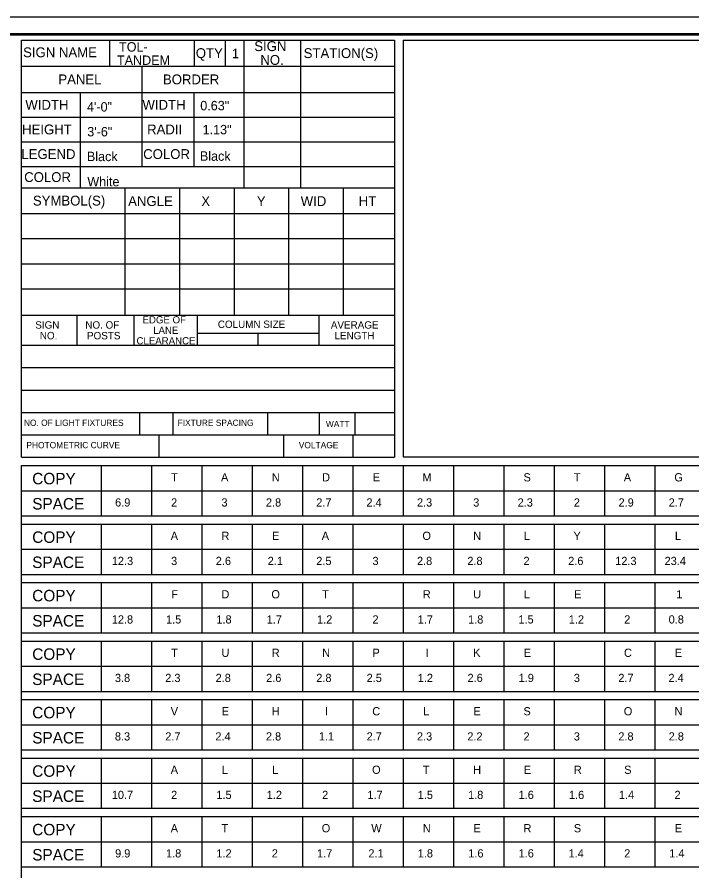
# Model space of a CAD drawing. Extents: x 17890484 to 17890754, y 17897495 to 17897992.
# Drawn here: x 17890564.9 to 17890605.3, y 17897547.8 to 17897598.9 of the extents above; entities that cross this region are included whole.
import ezdxf

# ---------------------------------------------------------------- set-up
doc = ezdxf.new("R2010")
doc.units = 0
for name, color, linetype in [('GSSign', 7, 'Continuous'), ('PlotBorder_dp', 7, 'Continuous'), ('SheetBorder_dp', 7, 'Continuous'), ('SheetLinesMisc1_dp', 7, 'Continuous'), ('SheetLinesMisc2_dp', 7, 'Continuous'), ('TextMinor', 7, 'Continuous')]:
    doc.layers.add(name, color=color, linetype=linetype)

msp = doc.modelspace()

# ---------------------------------------------------------------- linework, layer by layer
at = {"layer": 'PlotBorder_dp'}
msp.add_lwpolyline([(17890483.9, 17897494.956), (17890645.649, 17897494.956), (17890645.649, 17897598.868), (17890483.9, 17897598.868)], close=True, dxfattribs=at)
at = {"layer": 'SheetBorder_dp'}
msp.add_line((17890489.292, 17897597.887), (17890640.258, 17897597.887), dxfattribs=at)
at = {"layer": 'SheetLinesMisc1_dp'}
for p, q in [((17890570.448, 17897595.928), (17890570.448, 17897597.496)), ((17890575.495, 17897597.496), (17890575.495, 17897595.928)), ((17890577.348, 17897597.496), (17890577.348, 17897595.928)), ((17890578.452, 17897597.496), (17890578.452, 17897588.662)), ((17890581.847, 17897597.496), (17890581.847, 17897588.662)), ((17890565.154, 17897595.928), (17890587.465, 17897595.928)), ((17890572.364, 17897595.928), (17890572.364, 17897589.926)), ((17890565.154, 17897594.359), (17890587.465, 17897594.359)), ((17890568.68, 17897594.359), (17890568.68, 17897588.662)), ((17890575.476, 17897594.344), (17890575.476, 17897589.926)), ((17890565.154, 17897592.887), (17890587.465, 17897592.887)), ((17890565.154, 17897591.415), (17890587.465, 17897591.415)), ((17890565.154, 17897589.942), (17890587.465, 17897589.942)), ((17890565.154, 17897588.662), (17890587.465, 17897588.662)), ((17890571.35, 17897588.662), (17890571.35, 17897581.043)), ((17890574.61, 17897588.662), (17890574.61, 17897581.043)), ((17890577.87, 17897588.662), (17890577.87, 17897581.043)), ((17890581.13, 17897588.633), (17890581.13, 17897581.043)), ((17890584.39, 17897588.633), (17890584.39, 17897581.043)), ((17890565.159, 17897587.129), (17890587.465, 17897587.129)), ((17890565.159, 17897585.625), (17890587.465, 17897585.625)), ((17890565.159, 17897584.122), (17890587.465, 17897584.122)), ((17890565.159, 17897582.619), (17890587.465, 17897582.619)), ((17890565.154, 17897581.043), (17890587.465, 17897581.043)), ((17890568.464, 17897581.043), (17890568.464, 17897579.246)), ((17890571.887, 17897581.043), (17890571.887, 17897579.246)), ((17890575.665, 17897581.043), (17890575.665, 17897579.246)), ((17890582.941, 17897581.043), (17890582.941, 17897579.246)), ((17890575.665, 17897579.965), (17890582.936, 17897579.965)), ((17890579.3, 17897579.965), (17890579.3, 17897579.246)), ((17890565.154, 17897579.246), (17890587.465, 17897579.246)), ((17890565.154, 17897577.911), (17890587.465, 17897577.911)), ((17890565.154, 17897576.575), (17890587.465, 17897576.575)), ((17890565.154, 17897575.24), (17890587.465, 17897575.24)), ((17890565.154, 17897573.904), (17890587.465, 17897573.904)), ((17890569.918, 17897572.057), (17890569.918, 17897569.051)), ((17890572.929, 17897572.057), (17890572.929, 17897569.051)), ((17890575.94, 17897572.057), (17890575.94, 17897569.051)), ((17890578.949, 17897572.057), (17890578.949, 17897569.051)), ((17890581.96, 17897572.057), (17890581.96, 17897569.051)), ((17890584.97, 17897572.057), (17890584.97, 17897569.051)), ((17890587.981, 17897572.057), (17890587.981, 17897569.051)), ((17890590.991, 17897572.057), (17890590.991, 17897569.051)), ((17890594.001, 17897572.057), (17890594.001, 17897569.051)), ((17890597.011, 17897572.057), (17890597.011, 17897569.051)), ((17890600.022, 17897572.057), (17890600.022, 17897569.051)), ((17890603.032, 17897572.057), (17890603.032, 17897569.051)), ((17890565.155, 17897570.553), (17890639.157, 17897570.554)), ((17890565.155, 17897569.051), (17890639.157, 17897569.051)), ((17890565.155, 17897568.561), (17890639.157, 17897568.561)), ((17890569.918, 17897568.561), (17890569.918, 17897565.554)), ((17890572.929, 17897568.561), (17890572.929, 17897565.554)), ((17890575.94, 17897568.561), (17890575.94, 17897565.554)), ((17890578.949, 17897568.561), (17890578.949, 17897565.554)), ((17890581.96, 17897568.561), (17890581.96, 17897565.554)), ((17890584.97, 17897568.561), (17890584.97, 17897565.554)), ((17890587.981, 17897568.561), (17890587.981, 17897565.554)), ((17890590.991, 17897568.561), (17890590.991, 17897565.554)), ((17890594.001, 17897568.561), (17890594.001, 17897565.554)), ((17890597.011, 17897568.561), (17890597.011, 17897565.554)), ((17890600.022, 17897568.561), (17890600.022, 17897565.554)), ((17890603.032, 17897568.561), (17890603.032, 17897565.554)), ((17890565.155, 17897567.057), (17890639.157, 17897567.057)), ((17890565.155, 17897565.554), (17890639.157, 17897565.554)), ((17890565.155, 17897565.064), (17890639.157, 17897565.064)), ((17890569.918, 17897565.064), (17890569.918, 17897562.057)), ((17890572.929, 17897565.064), (17890572.929, 17897562.057)), ((17890575.94, 17897565.064), (17890575.94, 17897562.057)), ((17890578.949, 17897565.064), (17890578.949, 17897562.057)), ((17890581.96, 17897565.064), (17890581.96, 17897562.057)), ((17890584.97, 17897565.064), (17890584.97, 17897562.057)), ((17890587.981, 17897565.064), (17890587.981, 17897562.057)), ((17890590.991, 17897565.064), (17890590.991, 17897562.057)), ((17890594.001, 17897565.064), (17890594.001, 17897562.057)), ((17890597.011, 17897565.064), (17890597.011, 17897562.057)), ((17890600.022, 17897565.064), (17890600.022, 17897562.057)), ((17890603.032, 17897565.064), (17890603.032, 17897562.057)), ((17890565.155, 17897563.561), (17890639.157, 17897563.561)), ((17890565.155, 17897562.057), (17890639.157, 17897562.057)), ((17890565.155, 17897561.567), (17890639.157, 17897561.567)), ((17890569.918, 17897561.567), (17890569.918, 17897558.561)), ((17890572.929, 17897561.567), (17890572.929, 17897558.561)), ((17890575.94, 17897561.567), (17890575.94, 17897558.561)), ((17890578.949, 17897561.567), (17890578.949, 17897558.561)), ((17890581.96, 17897561.567), (17890581.96, 17897558.561)), ((17890584.97, 17897561.567), (17890584.97, 17897558.561)), ((17890587.981, 17897561.567), (17890587.981, 17897558.561)), ((17890590.991, 17897561.567), (17890590.991, 17897558.561)), ((17890594.001, 17897561.567), (17890594.001, 17897558.561)), ((17890597.011, 17897561.567), (17890597.011, 17897558.561)), ((17890600.022, 17897561.567), (17890600.022, 17897558.561)), ((17890603.032, 17897561.567), (17890603.032, 17897558.561)), ((17890565.155, 17897560.064), (17890639.157, 17897560.064)), ((17890565.155, 17897558.561), (17890639.157, 17897558.561)), ((17890565.155, 17897558.07), (17890639.157, 17897558.07)), ((17890569.918, 17897558.07), (17890569.918, 17897555.064)), ((17890572.929, 17897558.07), (17890572.929, 17897555.064)), ((17890575.94, 17897558.07), (17890575.94, 17897555.064)), ((17890578.949, 17897558.07), (17890578.949, 17897555.064)), ((17890581.96, 17897558.07), (17890581.96, 17897555.064)), ((17890584.97, 17897558.07), (17890584.97, 17897555.064)), ((17890587.981, 17897558.07), (17890587.981, 17897555.064)), ((17890590.991, 17897558.07), (17890590.991, 17897555.064)), ((17890594.001, 17897558.07), (17890594.001, 17897555.064)), ((17890597.011, 17897558.07), (17890597.011, 17897555.064)), ((17890600.022, 17897558.07), (17890600.022, 17897555.064)), ((17890603.032, 17897558.07), (17890603.032, 17897555.064)), ((17890565.155, 17897556.568), (17890639.157, 17897556.568)), ((17890565.155, 17897555.064), (17890639.157, 17897555.064)), ((17890565.155, 17897554.574), (17890639.157, 17897554.574)), ((17890569.918, 17897554.574), (17890569.918, 17897551.568)), ((17890572.929, 17897554.574), (17890572.929, 17897551.568)), ((17890575.94, 17897554.574), (17890575.94, 17897551.568)), ((17890578.949, 17897554.574), (17890578.949, 17897551.568)), ((17890581.96, 17897554.574), (17890581.96, 17897551.568)), ((17890584.97, 17897554.574), (17890584.97, 17897551.568)), ((17890587.981, 17897554.574), (17890587.981, 17897551.568)), ((17890590.991, 17897554.574), (17890590.991, 17897551.568)), ((17890594.001, 17897554.574), (17890594.001, 17897551.568)), ((17890597.011, 17897554.574), (17890597.011, 17897551.568)), ((17890600.022, 17897554.574), (17890600.022, 17897551.568)), ((17890603.032, 17897554.574), (17890603.032, 17897551.568)), ((17890565.155, 17897553.071), (17890639.157, 17897553.071)), ((17890565.155, 17897551.568), (17890639.157, 17897551.568)), ((17890565.155, 17897551.078), (17890639.157, 17897551.078)), ((17890569.918, 17897551.078), (17890569.918, 17897548.072)), ((17890572.929, 17897551.078), (17890572.929, 17897548.072)), ((17890575.94, 17897551.078), (17890575.94, 17897548.072)), ((17890578.949, 17897551.078), (17890578.949, 17897548.072)), ((17890581.96, 17897551.078), (17890581.96, 17897548.072)), ((17890584.97, 17897551.078), (17890584.97, 17897548.072)), ((17890587.981, 17897551.078), (17890587.981, 17897548.072)), ((17890590.991, 17897551.078), (17890590.991, 17897548.072)), ((17890594.001, 17897551.078), (17890594.001, 17897548.072)), ((17890597.011, 17897551.078), (17890597.011, 17897548.072)), ((17890600.022, 17897551.078), (17890600.022, 17897548.072)), ((17890603.032, 17897551.078), (17890603.032, 17897548.072)), ((17890565.155, 17897549.574), (17890639.157, 17897549.574)), ((17890565.155, 17897548.072), (17890639.157, 17897548.072))]:
    msp.add_line(p, q, dxfattribs=at)
at = {"layer": 'SheetLinesMisc2_dp'}
for p, q in [((17890489.413, 17897597.808), (17890639.869, 17897597.808)), ((17890565.154, 17897597.496), (17890587.465, 17897597.496)), ((17890565.154, 17897572.568), (17890565.154, 17897597.496)), ((17890565.154, 17897597.496), (17890587.465, 17897597.496)), ((17890587.465, 17897597.496), (17890587.465, 17897572.568)), ((17890587.978, 17897597.496), (17890639.15, 17897597.496)), ((17890587.978, 17897597.496), (17890587.978, 17897572.57)), ((17890565.154, 17897575.239), (17890587.46, 17897575.239)), ((17890572.212, 17897575.239), (17890572.212, 17897573.904)), ((17890574.205, 17897575.239), (17890574.205, 17897573.904)), ((17890579.88, 17897575.239), (17890579.88, 17897573.904)), ((17890582.966, 17897575.239), (17890582.966, 17897573.904)), ((17890585.096, 17897575.239), (17890585.096, 17897573.904)), ((17890565.154, 17897573.904), (17890587.46, 17897573.904)), ((17890573.382, 17897573.904), (17890573.382, 17897572.568)), ((17890580.825, 17897573.904), (17890580.825, 17897572.568)), ((17890584.966, 17897573.904), (17890584.966, 17897572.568)), ((17890565.154, 17897572.568), (17890587.46, 17897572.568)), ((17890565.154, 17897572.568), (17890587.465, 17897572.568)), ((17890587.978, 17897572.57), (17890639.15, 17897572.57)), ((17890565.155, 17897551.569), (17890565.155, 17897572.057)), ((17890565.155, 17897572.057), (17890639.157, 17897572.057)), ((17890565.155, 17897506.112), (17890565.155, 17897572.057))]:
    msp.add_line(p, q, dxfattribs=at)

# ---------------------------------------------------------------- texts
at = {"layer": 'GSSign'}
for s, height, p in [('TOL-', 0.5624, (17890570.995, 17897596.805)), ('TANDEM', 0.5624, (17890570.87, 17897596.009)), ('1', 0.562, (17890577.744, 17897596.411)), ('4\'-0"', 0.5624, (17890569.079, 17897593.22)), ('0.63"', 0.5624, (17890575.852, 17897593.295)), ('1.13"', 0.5624, (17890575.992, 17897591.861)), ('3\'-6"', 0.5624, (17890569.095, 17897591.736)), ('Black', 0.5624, (17890569.073, 17897590.255)), ('Black', 0.5624, (17890575.829, 17897590.277)), ('White', 0.5624, (17890569.098, 17897588.751)), ('T', 0.49, (17890574.108, 17897571.111)), ('A', 0.49, (17890577.095, 17897571.111)), ('N', 0.49, (17890580.129, 17897571.111)), ('D', 0.49, (17890583.14, 17897571.111)), ('E', 0.49, (17890586.162, 17897571.111)), ('M', 0.49, (17890589.137, 17897571.111)), ('S', 0.49, (17890595.181, 17897571.111)), ('T', 0.49, (17890598.191, 17897571.111)), ('A', 0.49, (17890601.178, 17897571.111)), ('G', 0.49, (17890604.201, 17897571.111)), ('6.9', 0.4902, (17890570.76, 17897569.608)), ('2', 0.49, (17890574.108, 17897569.608)), ('3', 0.49, (17890577.119, 17897569.608)), ('2.8', 0.4902, (17890579.779, 17897569.608)), ('2.7', 0.4902, (17890582.789, 17897569.608)), ('2.4', 0.4902, (17890585.788, 17897569.608)), ('2.3', 0.4902, (17890588.81, 17897569.608)), ('3', 0.49, (17890592.171, 17897569.608)), ('2.3', 0.4902, (17890594.831, 17897569.608)), ('2', 0.49, (17890598.191, 17897569.608)), ('2.9', 0.4902, (17890600.863, 17897569.608)), ('2.7', 0.4902, (17890603.862, 17897569.608)), ('A', 0.49, (17890574.085, 17897567.615)), ('R', 0.49, (17890577.119, 17897567.615)), ('E', 0.49, (17890580.141, 17897567.615)), ('A', 0.49, (17890583.116, 17897567.615)), ('O', 0.49, (17890589.137, 17897567.615)), ('N', 0.49, (17890592.171, 17897567.615)), ('L', 0.49, (17890595.204, 17897567.615)), ('Y', 0.49, (17890598.168, 17897567.615)), ('L', 0.49, (17890604.236, 17897567.615)), ('12.3', 0.4902, (17890570.561, 17897566.112)), ('3', 0.49, (17890574.108, 17897566.112)), ('2.6', 0.4902, (17890576.78, 17897566.112)), ('2.1', 0.4902, (17890579.884, 17897566.112)), ('2.5', 0.4902, (17890582.789, 17897566.112)), ('3', 0.49, (17890586.15, 17897566.112)), ('2.8', 0.4902, (17890588.81, 17897566.112)), ('2.8', 0.4902, (17890591.821, 17897566.112)), ('2', 0.49, (17890595.181, 17897566.112)), ('2.6', 0.4902, (17890597.853, 17897566.112)), ('12.3', 0.4902, (17890600.665, 17897566.112)), ('23.4', 0.4902, (17890603.617, 17897566.112)), ('F', 0.49, (17890574.12, 17897564.119)), ('D', 0.49, (17890577.119, 17897564.119)), ('O', 0.49, (17890580.106, 17897564.119)), ('T', 0.49, (17890583.14, 17897564.119)), ('R', 0.49, (17890589.16, 17897564.119)), ('U', 0.49, (17890592.171, 17897564.119)), ('L', 0.49, (17890595.204, 17897564.119)), ('E', 0.49, (17890598.203, 17897564.119)), ('1', 0.49, (17890604.317, 17897564.119)), ('12.8', 0.4902, (17890570.561, 17897562.616)), ('1.5', 0.4902, (17890573.805, 17897562.616)), ('1.8', 0.4902, (17890576.815, 17897562.616)), ('1.7', 0.4902, (17890579.826, 17897562.616)), ('1.2', 0.4902, (17890582.836, 17897562.616)), ('2', 0.49, (17890586.15, 17897562.616)), ('1.7', 0.4902, (17890588.857, 17897562.616)), ('1.8', 0.4902, (17890591.867, 17897562.616)), ('1.5', 0.4902, (17890594.878, 17897562.616)), ('1.2', 0.4902, (17890597.888, 17897562.616)), ('2', 0.49, (17890601.202, 17897562.616)), ('0.8', 0.4902, (17890603.862, 17897562.616)), ('T', 0.49, (17890574.108, 17897560.622)), ('U', 0.49, (17890577.119, 17897560.622)), ('R', 0.49, (17890580.129, 17897560.622)), ('N', 0.49, (17890583.14, 17897560.622)), ('P', 0.49, (17890586.15, 17897560.622)), ('I', 0.49, (17890589.324, 17897560.622)), ('K', 0.49, (17890592.171, 17897560.622)), ('E', 0.49, (17890595.193, 17897560.622)), ('C', 0.49, (17890601.19, 17897560.622)), ('E', 0.49, (17890604.224, 17897560.622)), ('3.8', 0.4902, (17890570.748, 17897559.119)), ('2.3', 0.4902, (17890573.758, 17897559.119)), ('2.8', 0.4902, (17890576.769, 17897559.119)), ('2.6', 0.4902, (17890579.791, 17897559.119)), ('2.8', 0.4902, (17890582.789, 17897559.119)), ('2.5', 0.4902, (17890585.8, 17897559.119)), ('1.2', 0.4902, (17890588.857, 17897559.119)), ('2.6', 0.4902, (17890591.832, 17897559.119)), ('1.9', 0.4902, (17890594.889, 17897559.119)), ('3', 0.49, (17890598.191, 17897559.119)), ('2.7', 0.4902, (17890600.852, 17897559.119)), ('2.4', 0.4902, (17890603.85, 17897559.119)), ('V', 0.49, (17890574.085, 17897557.126)), ('E', 0.49, (17890577.13, 17897557.126)), ('H', 0.49, (17890580.129, 17897557.126)), ('I', 0.49, (17890583.303, 17897557.126)), ('C', 0.49, (17890586.138, 17897557.126)), ('L', 0.49, (17890589.184, 17897557.126)), ('E', 0.49, (17890592.182, 17897557.126)), ('S', 0.49, (17890595.181, 17897557.126)), ('O', 0.49, (17890601.178, 17897557.126)), ('N', 0.49, (17890604.212, 17897557.126)), ('8.3', 0.4902, (17890570.748, 17897555.623)), ('2.7', 0.4902, (17890573.758, 17897555.623)), ('2.4', 0.4902, (17890576.757, 17897555.623)), ('2.8', 0.4902, (17890579.779, 17897555.623)), ('1.1', 0.4902, (17890582.941, 17897555.623)), ('2.7', 0.4902, (17890585.8, 17897555.623)), ('2.3', 0.4902, (17890588.81, 17897555.623)), ('2.2', 0.4902, (17890591.821, 17897555.623)), ('2', 0.49, (17890595.181, 17897555.623)), ('3', 0.49, (17890598.191, 17897555.623)), ('2.8', 0.4902, (17890600.852, 17897555.623)), ('2.8', 0.4902, (17890603.862, 17897555.623)), ('A', 0.49, (17890574.085, 17897553.63)), ('L', 0.49, (17890577.142, 17897553.63)), ('L', 0.49, (17890580.153, 17897553.63)), ('O', 0.49, (17890586.127, 17897553.63)), ('T', 0.49, (17890589.16, 17897553.63)), ('H', 0.49, (17890592.171, 17897553.63)), ('E', 0.49, (17890595.193, 17897553.63)), ('R', 0.49, (17890598.191, 17897553.63)), ('S', 0.49, (17890601.202, 17897553.63)), ('10.7', 0.4902, (17890570.561, 17897552.127)), ('2', 0.49, (17890574.108, 17897552.127)), ('1.5', 0.4902, (17890576.815, 17897552.127)), ('1.2', 0.4902, (17890579.826, 17897552.127)), ('2', 0.49, (17890583.14, 17897552.127)), ('1.7', 0.4902, (17890585.847, 17897552.127)), ('1.5', 0.4902, (17890588.857, 17897552.127)), ('1.8', 0.4902, (17890591.867, 17897552.127)), ('1.6', 0.4902, (17890594.889, 17897552.127)), ('1.6', 0.4902, (17890597.9, 17897552.127)), ('1.4', 0.4902, (17890600.887, 17897552.127)), ('2', 0.49, (17890604.212, 17897552.127)), ('A', 0.49, (17890574.085, 17897550.134)), ('T', 0.49, (17890577.119, 17897550.134)), ('O', 0.49, (17890583.116, 17897550.134)), ('W', 0.49, (17890586.08, 17897550.134)), ('N', 0.49, (17890589.16, 17897550.134)), ('E', 0.49, (17890592.182, 17897550.134)), ('R', 0.49, (17890595.181, 17897550.134)), ('S', 0.49, (17890598.191, 17897550.134)), ('E', 0.49, (17890604.224, 17897550.134)), ('9.9', 0.4902, (17890570.76, 17897548.631)), ('1.8', 0.4902, (17890573.805, 17897548.631)), ('1.2', 0.4902, (17890576.815, 17897548.631)), ('2', 0.49, (17890580.129, 17897548.631)), ('1.7', 0.4902, (17890582.836, 17897548.631)), ('2.1', 0.4902, (17890585.905, 17897548.631)), ('1.8', 0.4902, (17890588.857, 17897548.631)), ('1.6', 0.4902, (17890591.879, 17897548.631)), ('1.6', 0.4902, (17890594.889, 17897548.631)), ('1.4', 0.4902, (17890597.876, 17897548.631)), ('2', 0.49, (17890601.202, 17897548.631)), ('1.4', 0.4902, (17890603.897, 17897548.631))]:
    msp.add_text(s, height=height, dxfattribs=at).set_placement(p)
at = {"layer": 'TextMinor'}
for s, height, p in [('SIGN NAME', 0.5882, (17890565.258, 17897596.467)), ('SIGN', 0.5882, (17890579.082, 17897596.835)), ('STATION(S)', 0.5882, (17890582.036, 17897596.418)), ('QTY', 0.5882, (17890575.586, 17897596.418)), ('NO.', 0.5882, (17890579.445, 17897596.012)), ('PANEL', 0.5882, (17890567.367, 17897594.849)), ('BORDER', 0.5882, (17890573.621, 17897594.849)), ('WIDTH', 0.5882, (17890565.394, 17897593.329)), ('WIDTH', 0.5882, (17890572.397, 17897593.329)), ('HEIGHT', 0.5882, (17890565.197, 17897591.857)), ('RADII', 0.5882, (17890572.673, 17897591.857)), ('LEGEND', 0.5882, (17890565.156, 17897590.384)), ('COLOR', 0.5882, (17890572.438, 17897590.384)), ('COLOR', 0.5882, (17890565.323, 17897589.008)), ('SYMBOL(S)', 0.5882, (17890565.844, 17897587.601)), ('ANGLE', 0.5882, (17890571.54, 17897587.572)), ('X', 0.588, (17890575.914, 17897587.572)), ('Y', 0.588, (17890579.235, 17897587.572)), ('WID', 0.5882, (17890581.861, 17897587.572)), ('HT', 0.5882, (17890585.328, 17897587.572)), ('SIGN', 0.4411, (17890565.987, 17897580.243)), ('NO. OF', 0.4411, (17890568.979, 17897580.243)), ('EDGE OF', 0.4313, (17890572.402, 17897580.556)), ('COLUMN SIZE', 0.44113, (17890576.903, 17897580.284)), ('AVERAGE', 0.4411, (17890583.661, 17897580.243)), ('LANE', 0.4313, (17890573.035, 17897579.929)), ('NO.', 0.4411, (17890566.259, 17897579.605)), ('POSTS', 0.4411, (17890569.079, 17897579.605)), ('CLEARANCE', 0.4313, (17890572.039, 17897579.302)), ('LENGTH', 0.4411, (17890583.878, 17897579.605)), ('NO. OF LIGHT FIXTURES', 0.37485, (17890565.307, 17897574.429)), ('FIXTURE SPACING', 0.37485, (17890574.498, 17897574.429)), ('WATT', 0.3749, (17890583.364, 17897574.355)), ('PHOTOMETRIC CURVE', 0.37485, (17890565.455, 17897573.094)), ('VOLTAGE', 0.3749, (17890581.744, 17897573.094)), ('COPY', 0.6862, (17890565.804, 17897570.936)), ('SPACE', 0.6862, (17890565.804, 17897569.432)), ('COPY', 0.6862, (17890565.804, 17897567.436)), ('SPACE', 0.6862, (17890565.804, 17897565.933)), ('COPY', 0.6862, (17890565.804, 17897563.94)), ('SPACE', 0.6862, (17890565.804, 17897562.436)), ('COPY', 0.6862, (17890565.804, 17897560.443)), ('SPACE', 0.6862, (17890565.804, 17897558.939)), ('COPY', 0.6862, (17890565.804, 17897556.947)), ('SPACE', 0.6862, (17890565.804, 17897555.444)), ('COPY', 0.6862, (17890565.804, 17897553.453)), ('SPACE', 0.6862, (17890565.804, 17897551.95)), ('COPY', 0.6862, (17890565.804, 17897549.953)), ('SPACE', 0.6862, (17890565.804, 17897548.45))]:
    msp.add_text(s, height=height, dxfattribs=at).set_placement(p)

doc.saveas('drawing.dxf')
